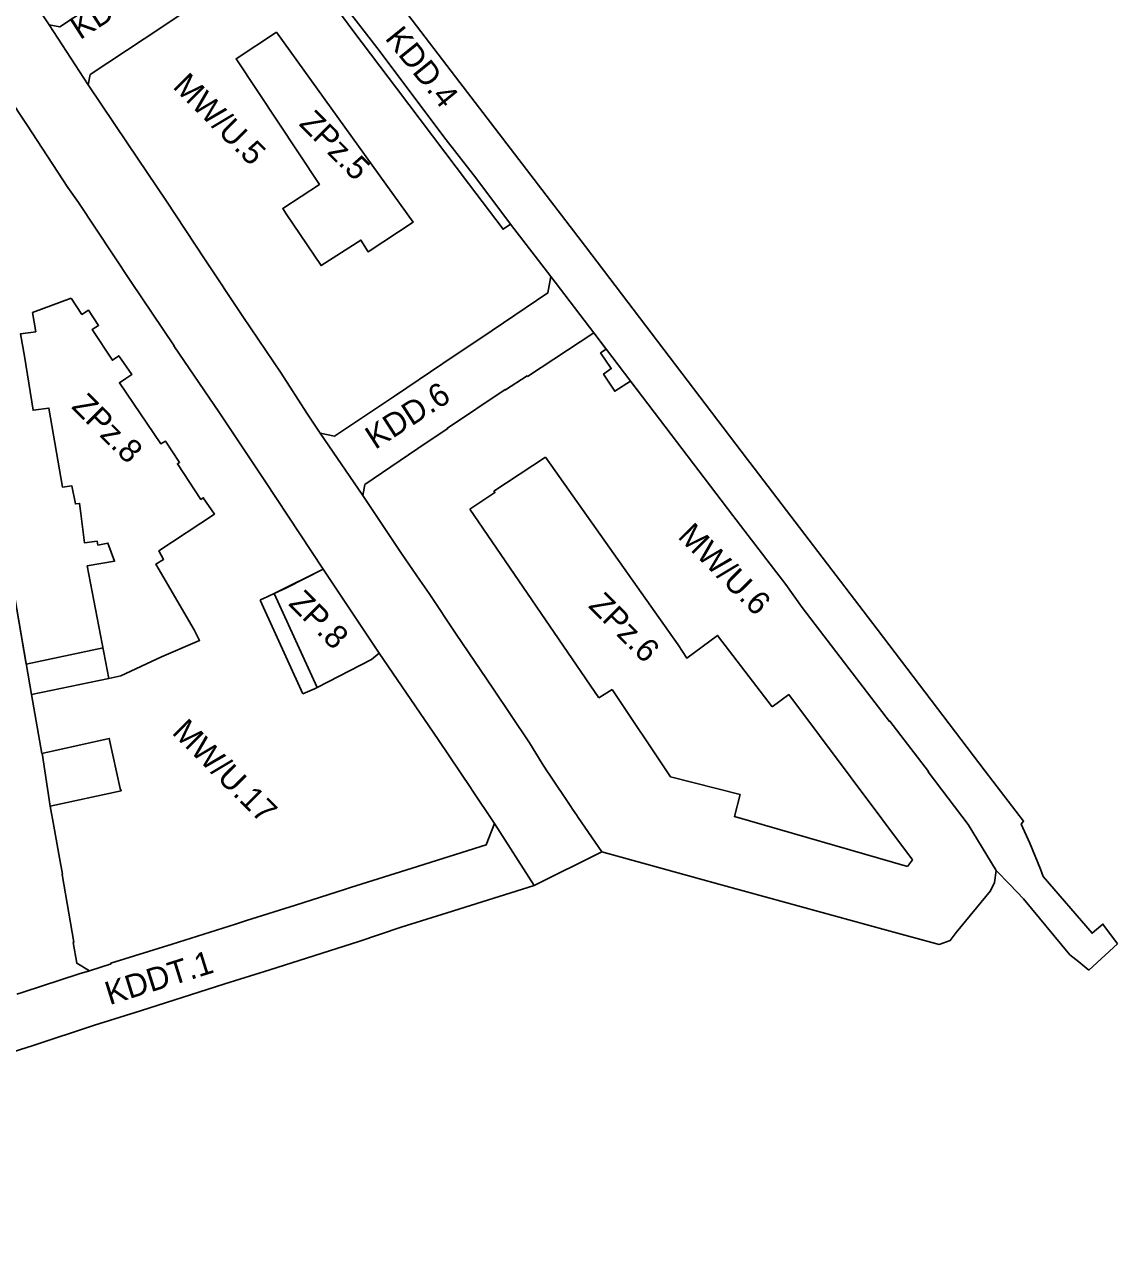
# Model space of a CAD drawing. Extents: x 7423835 to 7425280, y 5546086 to 5547600.
# Drawn here: x 7424769.7 to 7425051.2, y 5546498.6 to 5546812.9 of the extents above; entities that cross this region are included whole.
import ezdxf

# ---------------------------------------------------------------- set-up
doc = ezdxf.new("R2010")
doc.units = 0
for name, color, linetype in [('linie rozgraniczające', 7, 'Continuous'), ('obowiazujace linie zabudowy', 7, 'Continuous'), ('przeznaczenia terenów', 7, 'Continuous')]:
    doc.layers.add(name, color=color, linetype=linetype)

msp = doc.modelspace()

# ---------------------------------------------------------------- linework, layer by layer
at = {"layer": 'linie rozgraniczające'}
for p, q in [((7424786.09, 5546797.3), (7424776.08, 5546812.76)), ((7424916.31, 5546733.49), (7424905.23, 5546747.94)), ((7424771.77, 5546738.65), (7424781.7, 5546742.36)), ((7424856.81, 5546691.54), (7424845.82, 5546707.62)), ((7424884.42, 5546688.02), (7424917.65, 5546639.45)), ((7424834.02, 5546666.32), (7424845.06, 5546642.15)), ((7424921.05, 5546641.64), (7424917.65, 5546639.45)), ((7424966.56, 5546640.27), (7424962.28, 5546637.11)), ((7424998.44, 5546597.76), (7424966.56, 5546640.27)), ((7424890.77, 5546607.06), (7424901, 5546591.13)), ((7424948.55, 5546591.43), (7424918.4, 5546599.75)), ((7424998.44, 5546597.76), (7424997.14, 5546596.03)), ((7425019.71, 5546594.98), (7425019.71, 5546594.98)), ((7425051.22, 5546576.08), (7425043.82, 5546569.36))]:
    msp.add_line(p, q, dxfattribs=at)
for points in [[(7424782.68, 5546927.96), (7424794.17, 5546912.72), (7424814.07, 5546886.73), (7424849.43, 5546840.34), (7424880.72, 5546799.4), (7424914.19, 5546755.67), (7424955.9, 5546700.79), (7424956.48, 5546700.03), (7424989.28, 5546657.1), (7425017.11, 5546620.55), (7425027.02, 5546607.7), (7425026.41, 5546606.94), (7425028.62, 5546602.03), (7425031.34, 5546595.35), (7425032.03, 5546593.47), (7425044.64, 5546578.83), (7425047.45, 5546581.17), (7425051.22, 5546576.08)], [(7424829.01, 5546847.64), (7424829.26, 5546847.06), (7424829.32, 5546846.5), (7424829.13, 5546845.93), (7424828.67, 5546845.44), (7424814.48, 5546836.02), (7424804.24, 5546829.19), (7424792.87, 5546821.59), (7424778.79, 5546812.22), (7424776.08, 5546812.76), (7424763.28, 5546831.71), (7424755.89, 5546842.74), (7424729.31, 5546882.78), (7424720.47, 5546895.98), (7424718.31, 5546899.16), (7424718.21, 5546899.08), (7424711.48, 5546909.17), (7424711.6, 5546909.26), (7424709.41, 5546912.56)], [(7424786.09, 5546797.3), (7424786.62, 5546799.97), (7424800.5, 5546809.13), (7424812.54, 5546817.17), (7424824.68, 5546825.24), (7424836.91, 5546833.46), (7424837.76, 5546833.8), (7424838.78, 5546833.86), (7424839.7, 5546833.59), (7424839.91, 5546833.48), (7424840.65, 5546832.81), (7424851.85, 5546818.04), (7424861.02, 5546806.19), (7424869.71, 5546794.61), (7424878.29, 5546783.18), (7424885.98, 5546773.34), (7424894.86, 5546761.45), (7424905.23, 5546747.94)], [(7424766.34, 5546670.29), (7424771.49, 5546640.27), (7424774.14, 5546625.14), (7424774.29, 5546625.17), (7424776.32, 5546611.55), (7424777.26, 5546606.39), (7424778.69, 5546598.25), (7424779.46, 5546594.03), (7424779.39, 5546593.97), (7424782.4, 5546576.5), (7424782.25, 5546576.45), (7424783.14, 5546571.1), (7424786.43, 5546569.18), (7424791.99, 5546570.95), (7424791.93, 5546571.11), (7424807.72, 5546576.05), (7424824.02, 5546581.18), (7424826.84, 5546582.09), (7424839.5, 5546586.09), (7424852.1, 5546590.12), (7424853.67, 5546590.59), (7424869.52, 5546595.58), (7424888.63, 5546601.59), (7424890.77, 5546607.06), (7424890.77, 5546607.06), (7424884.83, 5546615.9), (7424884.7, 5546616.07), (7424876.2, 5546628.72), (7424861.01, 5546650.96), (7424846.6, 5546672.62), (7424831.58, 5546695.37), (7424819.89, 5546712.81), (7424808.16, 5546730.06), (7424808.24, 5546730.12), (7424797.07, 5546746.66), (7424783.59, 5546767.03), (7424780.9, 5546770.92), (7424770.35, 5546786.91), (7424760.14, 5546802.21)], [(7424786.09, 5546797.3), (7424796.33, 5546782.12), (7424806.28, 5546767.39), (7424816.04, 5546752.52), (7424825.95, 5546737.67), (7424835.8, 5546723.1), (7424842.45, 5546712.73), (7424845.82, 5546707.62)], [(7424905.23, 5546747.94), (7424904.52, 5546743.75), (7424890.11, 5546734.05), (7424877.48, 5546725.53), (7424865, 5546717.15), (7424849.53, 5546706.85), (7424845.82, 5546707.62)], [(7424781.7, 5546742.36), (7424784.48, 5546738.2), (7424784.48, 5546738.2), (7424784.48, 5546738.2), (7424784.48, 5546738.2), (7424786.14, 5546739.31), (7424788.76, 5546735.38), (7424787.09, 5546734.28), (7424792.36, 5546726.38), (7424793.99, 5546727.54), (7424797.37, 5546722.74), (7424795.82, 5546721.69), (7424794.16, 5546720.58), (7424804.85, 5546704.84), (7424805.98, 5546705.59), (7424809.64, 5546700.06), (7424809.09, 5546699.72), (7424815.13, 5546690.57), (7424815.74, 5546690.99), (7424818.61, 5546686.79), (7424804.32, 5546677.35), (7424805.51, 5546675.1), (7424803.49, 5546673.84), (7424813.39, 5546656.93), (7424814.77, 5546654.22), (7424804.95, 5546650.05), (7424794.5, 5546645.09), (7424791.44, 5546644.44), (7424785.87, 5546673.44), (7424792.91, 5546674.61), (7424791.2, 5546679.31), (7424788.61, 5546678.78), (7424788.39, 5546679.83), (7424785.18, 5546679.33), (7424784.21, 5546686.89), (7424783.87, 5546689.54), (7424782.8, 5546689.4), (7424781.91, 5546694.03), (7424779.51, 5546693.68), (7424775.97, 5546714.09), (7424771.89, 5546713.53), (7424769.71, 5546727.43), (7424768.63, 5546733.16), (7424772.59, 5546733.72), (7424771.77, 5546738.65)], [(7424787.09, 5546734.28), (7424787.39, 5546734.48), (7424788.76, 5546735.38)], [(7424916.31, 5546733.49), (7424899.28, 5546722.23), (7424899.15, 5546722.41), (7424893.57, 5546718.74), (7424893.47, 5546718.88), (7424878.61, 5546708.94), (7424878.7, 5546708.81), (7424873.13, 5546705.08), (7424857.37, 5546694.38), (7424856.81, 5546691.54), (7424866.82, 5546676.66), (7424871.5, 5546669.79), (7424873.94, 5546666.34), (7424880.87, 5546655.89), (7424880.89, 5546655.81), (7424890.34, 5546641.92), (7424899.75, 5546627.88), (7424903.02, 5546622.51), (7424903.44, 5546621.88), (7424904.41, 5546620.41), (7424904.85, 5546619.76), (7424910.41, 5546611.44), (7424910.85, 5546610.79), (7424911.84, 5546609.35), (7424912.26, 5546608.67), (7424918.4, 5546599.75)], [(7425019.91, 5546595.02), (7425012.76, 5546606.79), (7425002.41, 5546620.4), (7425002.53, 5546620.48), (7424992.58, 5546633.46), (7424992.47, 5546633.38), (7424982.03, 5546646.97), (7424969.99, 5546662.73), (7424965.76, 5546668.61), (7424961.76, 5546673.85), (7424952.16, 5546686.4), (7424928.83, 5546716.93), (7424916.31, 5546733.49)], [(7424903.87, 5546701.44), (7424890.61, 5546692.65), (7424890.84, 5546692.33), (7424884.42, 5546688.02)], [(7424903.87, 5546701.44), (7424938.01, 5546653.09), (7424940.27, 5546649.67), (7424948.16, 5546655.53), (7424962.28, 5546637.11)], [(7424834.02, 5546666.32), (7424836.97, 5546667.73), (7424846.6, 5546672.62)], [(7424861.01, 5546650.96), (7424859.1, 5546649.32), (7424845.06, 5546642.15)], [(7424954.04, 5546614.53), (7424936.05, 5546619.15), (7424921.05, 5546641.64)], [(7424954.04, 5546614.53), (7424952.52, 5546608.86), (7424997.14, 5546596.03)], [(7424918.4, 5546599.75), (7424918.38, 5546599.75), (7424900.98, 5546591.12), (7424878.58, 5546584.06), (7424866.75, 5546580.41), (7424855.79, 5546576.7), (7424832.92, 5546569.44), (7424821.32, 5546565.8), (7424799.61, 5546558.88), (7424787.74, 5546555.12), (7424771.89, 5546549.92), (7424768.38, 5546548.76), (7424743.55, 5546540.92), (7424698.14, 5546526.8), (7424663.53, 5546515.44), (7424659.14, 5546514), (7424649.3, 5546510.78), (7424646.94, 5546509.94), (7424595.52, 5546492.88), (7424562.11, 5546482.06)], [(7425043.82, 5546569.36), (7425041.24, 5546571.43), (7425038.9, 5546573.3), (7425027, 5546587.7), (7425023.45, 5546591.36), (7425019.91, 5546595.02), (7425019.53, 5546591.91), (7425018.52, 5546589.72), (7425009.64, 5546579), (7425008.11, 5546576.92), (7425005.24, 5546575.97), (7424991.7, 5546579.66), (7424961.05, 5546588.01), (7424948.55, 5546591.43)], [(7424786.43, 5546569.18), (7424783.77, 5546568.34), (7424769.33, 5546563.69), (7424767.74, 5546563.16)]]:
    msp.add_lwpolyline(points, dxfattribs=at)
msp.add_lwpolyline([(7424834.61, 5546810.89), (7424869.77, 5546761.93), (7424858.17, 5546754.35), (7424856.34, 5546757.35), (7424846.09, 5546750.76), (7424837.09, 5546764.13), (7424836.19, 5546765.5), (7424845.65, 5546771.65), (7424824.2, 5546804.02)], close=True, dxfattribs=at)
at = {"layer": 'obowiazujace linie zabudowy'}
msp.add_line((7424770.14, 5546648.15), (7424789.93, 5546652.3), dxfattribs=at)
for points in [[(7424763.28, 5546831.71), (7424776.08, 5546812.76), (7424778.79, 5546812.22), (7424792.87, 5546821.59)], [(7424905.23, 5546747.94), (7424894.86, 5546761.45), (7424892.94, 5546760.14), (7424884.03, 5546771.93), (7424865.53, 5546796.43), (7424854.53, 5546810.99), (7424850.14, 5546816.92), (7424851.85, 5546818.04), (7424840.65, 5546832.81), (7424839.91, 5546833.48), (7424839.7, 5546833.59), (7424838.78, 5546833.86), (7424837.76, 5546833.8), (7424836.91, 5546833.46), (7424824.68, 5546825.24), (7424812.54, 5546817.17), (7424800.5, 5546809.13), (7424786.62, 5546799.97), (7424786.09, 5546797.3)], [(7424846.6, 5546672.62), (7424831.58, 5546695.37), (7424819.89, 5546712.81), (7424808.16, 5546730.06), (7424808.24, 5546730.12), (7424797.07, 5546746.66), (7424783.59, 5546767.03), (7424780.9, 5546770.92), (7424770.35, 5546786.91), (7424760.14, 5546802.21)], [(7424786.09, 5546797.3), (7424796.33, 5546782.12), (7424806.28, 5546767.39), (7424816.04, 5546752.52), (7424825.95, 5546737.67), (7424835.8, 5546723.1), (7424842.45, 5546712.73), (7424845.82, 5546707.62)], [(7424845.82, 5546707.62), (7424849.53, 5546706.85), (7424865, 5546717.15), (7424877.48, 5546725.53), (7424890.11, 5546734.05), (7424904.52, 5546743.75), (7424905.23, 5546747.94)], [(7424916.31, 5546733.49), (7424899.28, 5546722.23), (7424899.15, 5546722.41), (7424893.57, 5546718.74), (7424893.47, 5546718.88), (7424878.61, 5546708.94), (7424878.7, 5546708.81), (7424873.13, 5546705.08), (7424857.37, 5546694.38), (7424856.81, 5546691.54), (7424866.82, 5546676.66), (7424871.5, 5546669.79), (7424873.94, 5546666.34), (7424880.87, 5546655.89), (7424880.89, 5546655.81), (7424890.34, 5546641.92), (7424899.75, 5546627.88), (7424903.02, 5546622.51), (7424903.44, 5546621.88), (7424904.41, 5546620.41), (7424904.85, 5546619.76), (7424910.41, 5546611.44), (7424910.85, 5546610.79), (7424911.84, 5546609.35), (7424912.26, 5546608.67), (7424918.4, 5546599.75)], [(7424919.53, 5546729.23), (7424916.31, 5546733.49)], [(7424925.73, 5546721.03), (7424921.71, 5546718.41), (7424918.83, 5546722.82), (7424920.81, 5546724.26), (7424918.07, 5546728.27), (7424919.53, 5546729.23)], [(7425019.91, 5546595.02), (7425012.76, 5546606.79), (7425002.41, 5546620.4), (7425002.53, 5546620.48), (7424992.58, 5546633.46), (7424992.47, 5546633.38), (7424982.03, 5546646.97), (7424969.99, 5546662.73), (7424965.76, 5546668.61), (7424961.76, 5546673.85), (7424952.16, 5546686.4), (7424928.83, 5546716.93), (7424925.73, 5546721.03)], [(7424830.37, 5546664.67), (7424831.09, 5546664.92), (7424834.02, 5546666.32), (7424846.6, 5546672.62)], [(7424766.34, 5546670.29), (7424770.14, 5546648.15)], [(7424841.39, 5546640.48), (7424830.43, 5546664.6)], [(7424776.32, 5546611.55), (7424777.26, 5546606.39), (7424778.69, 5546598.25), (7424779.46, 5546594.03), (7424779.39, 5546593.97), (7424782.4, 5546576.5), (7424782.25, 5546576.45), (7424783.14, 5546571.1), (7424786.43, 5546569.18), (7424791.99, 5546570.95), (7424791.93, 5546571.11), (7424807.72, 5546576.05), (7424824.02, 5546581.18), (7424826.84, 5546582.09), (7424839.5, 5546586.09), (7424852.1, 5546590.12), (7424853.67, 5546590.59), (7424869.52, 5546595.58), (7424888.63, 5546601.59), (7424890.77, 5546607.06), (7424890.77, 5546607.06), (7424884.83, 5546615.9), (7424884.7, 5546616.07), (7424876.2, 5546628.72), (7424861.01, 5546650.96)], [(7424861.01, 5546650.96), (7424859.1, 5546649.32), (7424845.06, 5546642.15), (7424844.36, 5546641.8), (7424841.39, 5546640.48)], [(7424791.44, 5546644.44), (7424771.49, 5546640.27), (7424774.14, 5546625.14)], [(7424774.14, 5546625.14), (7424791.54, 5546629), (7424794.33, 5546616.14), (7424794.56, 5546615.46), (7424776.32, 5546611.55)]]:
    msp.add_lwpolyline(points, dxfattribs=at)

# ---------------------------------------------------------------- texts
at = {"layer": 'przeznaczenia terenów'}
for s, rotation, p in [('KDD.5', 32.8514, (7424783.99, 5546808.8)), ('KDD.4', 308.9867, (7424862.35, 5546809.25)), ('MW/U.5', 314.9764, (7424807.64, 5546796.66)), ('ZPz.5', 314.9764, (7424840.18, 5546787.1)), ('KDD.6', 32.8514, (7424860.01, 5546703.27)), ('ZPz.8', 314.9764, (7424781.6, 5546714.25)), ('MW/U.6', 314.9764, (7424937.68, 5546680.79)), ('ZP.8', 314.9764, (7424837.45, 5546663.51)), ('ZPz.6', 314.9764, (7424914.7, 5546662.93)), ('MW/U.17', 314.9764, (7424807.4, 5546630.35)), ('KDDT.1', 17.3962, (7424791.59, 5546560.28))]:
    msp.add_text(s, height=6, rotation=rotation, dxfattribs=at).set_placement(p)

doc.saveas('drawing.dxf')
